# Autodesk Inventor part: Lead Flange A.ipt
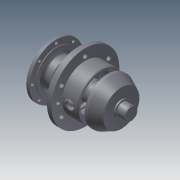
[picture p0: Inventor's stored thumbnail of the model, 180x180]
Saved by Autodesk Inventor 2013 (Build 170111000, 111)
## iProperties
Created: 2005-03
Part Number: Lead Flange A.ipt
Material: Steel, Mild
Document SubType Name: Modeling
Designer: salex
Manufacturer: Standard
Standards Organization: Custom
Density: 7.86 g/cm^3
Mass: 19576 g
Surface Area: 3298.53 cm^2
Volume: 2490.58 cm^3
Author: salex
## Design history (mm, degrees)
body "Solid1"
derived "B138 02 00 080.iam"
node "B138 02 00 180.iam:1::B138 02 00 182.iam:1::B138 02 00 182 P"
node "B138 02 00 180.iam:1::B138 02 00 181.ipt:1"
node "B138 02 00 088.ipt:1"
node "B138 02 00 081.ipt:1"
node "B138 02 00 082.ipt:1"
node "B138 02 00 171.ipt:1"
node "B138 02 00 089.ipt:1"
